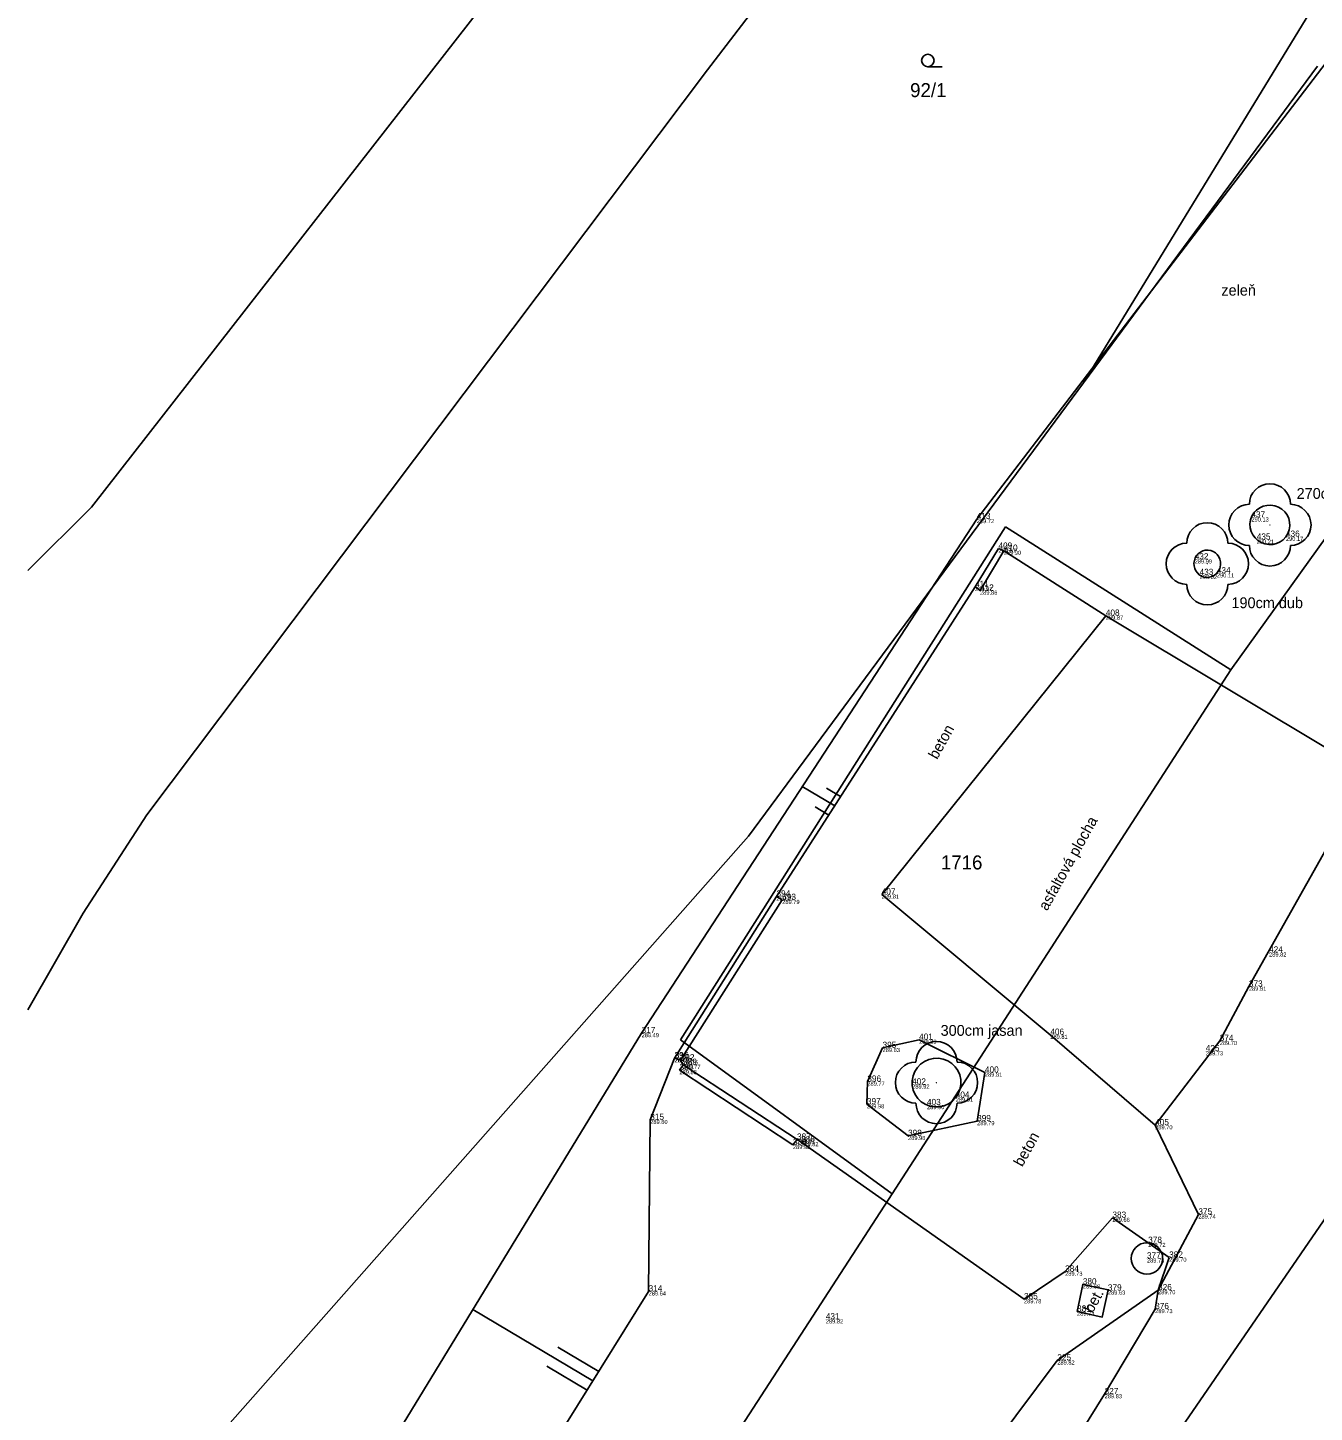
# Model space of a CAD drawing. Extents: x -805057 to -804930, y -994399 to -994240.
# Drawn here: x -805055.46 to -805024.17, y -994307.89 to -994274.22 of the extents above; entities that cross this region are included whole.
import ezdxf

# ---------------------------------------------------------------- set-up
doc = ezdxf.new("R2010")
doc.units = 0
for name, color, linetype in [('bod cislo', 7, 'Continuous'), ('bod pozice', 7, 'Continuous'), ('bod výška', 7, 'Continuous'), ('kanalizace', 7, 'Continuous'), ('Katastralni mapa', 7, 'Continuous'), ('komunikace', 7, 'Continuous'), ('plot', 7, 'Continuous'), ('popis', 7, 'Continuous'), ('strom', 7, 'Continuous'), ('svah', 7, 'Continuous'), ('šrafy', 7, 'Continuous')]:
    doc.layers.add(name, color=color, linetype=linetype)

msp = doc.modelspace()

# ---------------------------------------------------------------- linework, layer by layer
at = {"layer": 'bod pozice'}
for p, q in [((-805032.38, -994286.17), (-805032.38, -994286.17)), ((-805025.7, -994286.13), (-805025.7, -994286.13)), ((-805025.57, -994286.67), (-805025.57, -994286.67)), ((-805024.86, -994286.6), (-805024.86, -994286.6)), ((-805031.85, -994286.89), (-805031.85, -994286.89)), ((-805031.72, -994286.94), (-805031.72, -994286.94)), ((-805027.08, -994287.15), (-805027.08, -994287.15)), ((-805026.96, -994287.53), (-805026.96, -994287.53)), ((-805026.54, -994287.49), (-805026.54, -994287.49)), ((-805032.42, -994287.82), (-805032.42, -994287.82)), ((-805032.3, -994287.91), (-805032.3, -994287.91)), ((-805029.24, -994288.52), (-805029.24, -994288.52)), ((-805037.25, -994295.35), (-805037.25, -994295.35)), ((-805037.11, -994295.43), (-805037.11, -994295.43)), ((-805034.69, -994295.3), (-805034.69, -994295.3)), ((-805025.27, -994296.71), (-805025.27, -994296.71)), ((-805025.76, -994297.54), (-805025.76, -994297.54)), ((-805040.53, -994298.67), (-805040.53, -994298.67)), ((-805030.59, -994298.71), (-805030.59, -994298.71)), ((-805034.67, -994299.03), (-805034.67, -994299.03)), ((-805033.78, -994298.83), (-805033.78, -994298.83)), ((-805026.81, -994299.11), (-805026.81, -994299.11)), ((-805026.47, -994298.86), (-805026.47, -994298.86)), ((-805039.73, -994299.28), (-805039.73, -994299.28)), ((-805039.72, -994299.28), (-805039.72, -994299.28)), ((-805039.58, -994299.33), (-805039.58, -994299.33)), ((-805039.52, -994299.44), (-805039.52, -994299.44)), ((-805039.61, -994299.57), (-805039.61, -994299.57)), ((-805032.18, -994299.63), (-805032.18, -994299.63)), ((-805035.04, -994299.85), (-805035.04, -994299.85)), ((-805033.95, -994299.92), (-805033.95, -994299.92)), ((-805035.05, -994300.4), (-805035.05, -994300.4)), ((-805033.59, -994300.42), (-805033.59, -994300.42)), ((-805032.89, -994300.24), (-805032.89, -994300.24)), ((-805040.32, -994300.78), (-805040.32, -994300.78)), ((-805032.37, -994300.81), (-805032.37, -994300.81)), ((-805034.05, -994301.17), (-805034.05, -994301.17)), ((-805028.04, -994300.91), (-805028.04, -994300.91)), ((-805036.85, -994301.39), (-805036.85, -994301.39)), ((-805036.75, -994301.26), (-805036.75, -994301.26)), ((-805036.65, -994301.32), (-805036.65, -994301.32)), ((-805029.08, -994303.16), (-805029.08, -994303.16)), ((-805026.99, -994303.08), (-805026.99, -994303.08)), ((-805028.21, -994303.77), (-805028.21, -994303.77)), ((-805028.24, -994304.15), (-805028.24, -994304.15)), ((-805027.7, -994304.13), (-805027.7, -994304.13)), ((-805030.23, -994304.47), (-805030.23, -994304.47)), ((-805029.8, -994304.78), (-805029.8, -994304.78)), ((-805040.36, -994304.95), (-805040.36, -994304.95)), ((-805031.23, -994305.14), (-805031.23, -994305.14)), ((-805029.19, -994304.93), (-805029.19, -994304.93)), ((-805027.97, -994304.92), (-805027.97, -994304.92)), ((-805029.94, -994305.44), (-805029.94, -994305.44)), ((-805028.04, -994305.38), (-805028.04, -994305.38)), ((-805036.05, -994305.63), (-805036.05, -994305.63)), ((-805030.42, -994306.63), (-805030.42, -994306.63)), ((-805029.27, -994307.45), (-805029.27, -994307.45))]:
    msp.add_line(p, q, dxfattribs=at)
at = {"layer": 'kanalizace'}
msp.add_circle((-805028.24, -994304.15), 0.382, dxfattribs=at)
at = {"layer": 'Katastralni mapa'}
for points in [[(-805018.71, -994264.73), (-805029.78, -994282.86)], [(-805031.83, -994265.99), (-805038.93, -994275.25)], [(-805043.31, -994272.29), (-805053.91, -994285.88)], [(-805033.57, -994275.17), (-805033.219, -994275.17)], [(-805024.09, -994275.16), (-805029.78, -994282.86)], [(-805038.93, -994275.25), (-805052.56, -994293.36)], [(-805029.78, -994282.86), (-805037.93, -994293.88)], [(-805055.46, -994287.421), (-805053.91, -994285.88)], [(-805023.45, -994286.01), (-805026.2, -994289.84)], [(-805031.68, -994286.36), (-805039.58, -994298.83)], [(-805026.2, -994289.84), (-805031.68, -994286.36)], [(-805034.44, -994302.58), (-805026.2, -994289.84)], [(-805052.56, -994293.36), (-805054.11, -994295.75)], [(-805037.93, -994293.88), (-805055.46, -994313.714)], [(-805054.11, -994295.75), (-805055.46, -994298.108)], [(-805039.58, -994298.83), (-805034.44, -994302.58)], [(-805046.31, -994320.89), (-805034.44, -994302.58)]]:
    msp.add_lwpolyline(points, dxfattribs=at)
msp.add_circle((-805033.569, -994275.02), 0.151, dxfattribs=at)
at = {"layer": 'komunikace'}
for p, q in [((-805032.42, -994287.82), (-805031.85, -994286.89)), ((-805031.72, -994286.94), (-805032.3, -994287.91)), ((-805031.85, -994286.89), (-805031.72, -994286.94)), ((-805031.72, -994286.94), (-805029.24, -994288.52)), ((-805037.25, -994295.35), (-805032.42, -994287.82)), ((-805032.3, -994287.91), (-805032.42, -994287.82)), ((-805034.69, -994295.3), (-805029.24, -994288.52)), ((-805029.24, -994288.52), (-805022.85, -994292.36)), ((-805025.76, -994297.54), (-805022.85, -994292.36)), ((-805039.73, -994299.28), (-805037.25, -994295.35)), ((-805037.11, -994295.43), (-805039.58, -994299.33)), ((-805037.25, -994295.35), (-805037.11, -994295.43)), ((-805034.69, -994295.3), (-805030.59, -994298.71)), ((-805026.47, -994298.86), (-805025.76, -994297.54)), ((-805030.59, -994298.71), (-805028.04, -994300.91)), ((-805034.67, -994299.03), (-805035.04, -994299.85)), ((-805033.78, -994298.83), (-805034.67, -994299.03)), ((-805032.18, -994299.63), (-805033.78, -994298.83)), ((-805026.47, -994298.86), (-805028.04, -994300.91)), ((-805039.58, -994299.33), (-805039.73, -994299.28)), ((-805039.61, -994299.57), (-805039.52, -994299.44)), ((-805039.52, -994299.44), (-805039.58, -994299.33)), ((-805039.52, -994299.44), (-805036.75, -994301.26)), ((-805036.85, -994301.39), (-805039.61, -994299.57)), ((-805032.18, -994299.63), (-805032.37, -994300.81)), ((-805035.04, -994299.85), (-805035.05, -994300.4)), ((-805035.05, -994300.4), (-805034.05, -994301.17)), ((-805028.28, -994309.54), (-805022, -994300.4)), ((-805034.05, -994301.17), (-805032.37, -994300.81)), ((-805026.99, -994303.08), (-805028.04, -994300.91)), ((-805036.75, -994301.26), (-805036.85, -994301.39)), ((-805036.65, -994301.32), (-805036.75, -994301.26)), ((-805031.23, -994305.14), (-805036.65, -994301.32)), ((-805030.23, -994304.47), (-805029.08, -994303.16)), ((-805029.08, -994303.16), (-805027.7, -994304.13)), ((-805027.97, -994304.92), (-805026.99, -994303.08)), ((-805027.7, -994304.13), (-805027.97, -994304.92)), ((-805031.23, -994305.14), (-805030.23, -994304.47)), ((-805028.04, -994305.38), (-805027.97, -994304.92)), ((-805029.27, -994307.45), (-805028.04, -994305.38)), ((-805033.55, -994314.32), (-805029.27, -994307.45))]:
    msp.add_line(p, q, dxfattribs=at)
msp.add_lwpolyline([(-805029.94, -994305.44), (-805029.8, -994304.78), (-805029.187, -994304.914), (-805029.327, -994305.574)], close=True, dxfattribs=at)
at = {"layer": 'plot'}
for p, q in [((-805040.53, -994298.67), (-805032.38, -994286.17)), ((-805047.18, -994309.56), (-805040.53, -994298.67))]:
    msp.add_line(p, q, dxfattribs=at)
msp.add_lwpolyline([(-805032.38, -994286.17), (-805016.94, -994265.99), (-805019.51, -994262.99)], dxfattribs=at)
at = {"layer": 'strom'}
for centre in [(-805025.25, -994286.312), (-805026.772, -994287.258), (-805033.358, -994299.874)]:
    msp.add_circle(centre, 0.0005, dxfattribs=at)
for centre, start, end in [((-805025.25, -994285.812), 0, 180), ((-805025.75, -994286.312), 90, 270), ((-805024.75, -994286.312), 270, 90), ((-805026.772, -994286.758), 0, 180), ((-805027.272, -994287.258), 90, 270), ((-805026.272, -994287.258), 270, 90), ((-805025.25, -994286.812), 180, 360), ((-805026.772, -994287.758), 180, 360), ((-805033.358, -994299.374), 0, 180), ((-805033.858, -994299.874), 90, 270), ((-805032.858, -994299.874), 270, 90), ((-805033.358, -994300.374), 180, 360)]:
    msp.add_arc(centre, 0.5, start, end, dxfattribs=at)
for centre, major_axis, ratio in [((-805025.25, -994286.312), (0.47, -0.121), 0.986953), ((-805026.772, -994287.258), (-0.017, -0.332), 0.977537), ((-805033.358, -994299.874), (0.592, -0.047), 0.999095)]:
    msp.add_ellipse(centre, major_axis=major_axis, ratio=ratio, dxfattribs=at)
at = {"layer": 'svah'}
for p, q in [((-805040.32, -994300.78), (-805039.73, -994299.28)), ((-805040.36, -994304.95), (-805040.32, -994300.78)), ((-805043.07, -994309.3), (-805040.36, -994304.95)), ((-805030.42, -994306.63), (-805027.97, -994304.92)), ((-805032.96, -994310.02), (-805030.42, -994306.63))]:
    msp.add_line(p, q, dxfattribs=at)
at = {"layer": 'šrafy'}
for p, q in [((-805035.834, -994293.142), (-805036.621, -994292.675)), ((-805035.693, -994292.916), (-805036.035, -994292.713)), ((-805035.975, -994293.37), (-805036.308, -994293.172)), ((-805041.715, -994307.125), (-805044.634, -994305.391)), ((-805041.574, -994306.899), (-805042.565, -994306.31)), ((-805041.857, -994307.352), (-805042.838, -994306.769))]:
    msp.add_line(p, q, dxfattribs=at)

# ---------------------------------------------------------------- texts
at = {"layer": 'bod cislo'}
for s, p in [('413    ', (-805032.38, -994286.17)), ('437    ', (-805025.7, -994286.13)), ('435    ', (-805025.57, -994286.67)), ('436    ', (-805024.86, -994286.6)), ('409    ', (-805031.85, -994286.89)), ('410    ', (-805031.72, -994286.94)), ('432    ', (-805027.08, -994287.15)), ('434    ', (-805026.54, -994287.49)), ('411    ', (-805032.42, -994287.82)), ('433    ', (-805026.96, -994287.53)), ('412    ', (-805032.3, -994287.91)), ('408    ', (-805029.24, -994288.52)), ('394    ', (-805037.25, -994295.35)), ('393    ', (-805037.11, -994295.43)), ('407    ', (-805034.69, -994295.3)), ('424    ', (-805025.27, -994296.71)), ('424    ', (-805025.27, -994296.71)), ('373    ', (-805025.76, -994297.54)), ('317    ', (-805040.53, -994298.67)), ('401    ', (-805033.78, -994298.83)), ('406    ', (-805030.59, -994298.71)), ('374    ', (-805026.47, -994298.86)), ('391    ', (-805039.73, -994299.28)), ('316    ', (-805039.72, -994299.28)), ('395    ', (-805034.67, -994299.03)), ('425    ', (-805026.81, -994299.11)), ('390    ', (-805039.61, -994299.57)), ('392    ', (-805039.58, -994299.33)), ('389    ', (-805039.52, -994299.44)), ('400    ', (-805032.18, -994299.63)), ('396    ', (-805035.04, -994299.85)), ('402    ', (-805033.95, -994299.92)), ('404    ', (-805032.89, -994300.24)), ('397    ', (-805035.05, -994300.4)), ('403    ', (-805033.59, -994300.42)), ('315    ', (-805040.32, -994300.78)), ('399    ', (-805032.37, -994300.81)), ('405    ', (-805028.04, -994300.91)), ('387    ', (-805036.75, -994301.26)), ('386    ', (-805036.65, -994301.32)), ('398    ', (-805034.05, -994301.17)), ('388    ', (-805036.85, -994301.39)), ('383    ', (-805029.08, -994303.16)), ('375    ', (-805026.99, -994303.08)), ('378    ', (-805028.21, -994303.77)), ('377    ', (-805028.24, -994304.15)), ('382    ', (-805027.7, -994304.13)), ('384    ', (-805030.23, -994304.47)), ('314    ', (-805040.36, -994304.95)), ('380    ', (-805029.8, -994304.78)), ('379    ', (-805029.19, -994304.93)), ('326    ', (-805027.97, -994304.92)), ('385    ', (-805031.23, -994305.14)), ('431    ', (-805036.05, -994305.63)), ('381    ', (-805029.94, -994305.44)), ('376    ', (-805028.04, -994305.38)), ('325    ', (-805030.42, -994306.63)), ('327    ', (-805029.27, -994307.45))]:
    msp.add_text(s, height=0.15, dxfattribs=at).set_placement(p)
at = {"layer": 'bod výška'}
for s, p in [('289.72  ', (-805032.38, -994286.27)), ('290.13  ', (-805025.7, -994286.23)), ('290.21  ', (-805025.57, -994286.77)), ('290.17  ', (-805024.86, -994286.7)), ('289.97  ', (-805031.85, -994286.99)), ('289.90  ', (-805031.72, -994287.04)), ('289.99  ', (-805027.08, -994287.25)), ('290.02  ', (-805026.96, -994287.63)), ('290.11  ', (-805026.54, -994287.59)), ('289.97  ', (-805032.42, -994287.92)), ('289.86  ', (-805032.3, -994288.01)), ('289.87  ', (-805029.24, -994288.62)), ('289.87  ', (-805037.25, -994295.45)), ('289.79  ', (-805037.11, -994295.53)), ('289.81  ', (-805034.69, -994295.4)), ('289.82  ', (-805025.27, -994296.81)), ('289.81  ', (-805025.76, -994297.64)), ('289.49  ', (-805040.53, -994298.77)), ('289.81  ', (-805030.59, -994298.81)), ('289.83  ', (-805034.67, -994299.13)), ('289.89  ', (-805033.78, -994298.93)), ('289.73  ', (-805026.81, -994299.21)), ('289.70  ', (-805026.47, -994298.96)), ('289.83  ', (-805039.73, -994299.38)), ('289.72  ', (-805039.72, -994299.38)), ('289.76  ', (-805039.58, -994299.43)), ('289.77  ', (-805039.52, -994299.54)), ('289.83  ', (-805039.61, -994299.67)), ('289.81  ', (-805032.18, -994299.73)), ('289.77  ', (-805035.04, -994299.95)), ('289.92  ', (-805033.95, -994300.02)), ('289.98  ', (-805035.05, -994300.5)), ('289.90  ', (-805033.59, -994300.52)), ('289.91  ', (-805032.89, -994300.34)), ('289.80  ', (-805040.32, -994300.88)), ('289.79  ', (-805032.37, -994300.91)), ('289.98  ', (-805034.05, -994301.27)), ('289.70  ', (-805028.04, -994301.01)), ('289.92  ', (-805036.85, -994301.49)), ('289.83  ', (-805036.75, -994301.36)), ('289.82  ', (-805036.65, -994301.42)), ('289.66  ', (-805029.08, -994303.26)), ('289.74  ', (-805026.99, -994303.18)), ('289.72  ', (-805028.21, -994303.87)), ('289.74  ', (-805028.24, -994304.25)), ('289.70  ', (-805027.7, -994304.23)), ('289.73  ', (-805030.23, -994304.57)), ('289.68  ', (-805029.8, -994304.88)), ('289.64  ', (-805040.36, -994305.05)), ('289.78  ', (-805031.23, -994305.24)), ('289.63  ', (-805029.19, -994305.03)), ('289.70  ', (-805027.97, -994305.02)), ('289.73  ', (-805029.94, -994305.54)), ('289.73  ', (-805028.04, -994305.48)), ('289.82  ', (-805036.05, -994305.73)), ('289.82  ', (-805030.42, -994306.73)), ('289.83  ', (-805029.27, -994307.55))]:
    msp.add_text(s, height=0.1, dxfattribs=at).set_placement(p)
at = {"layer": 'Katastralni mapa'}
for s, p in [('92/1', (-805034, -994275.91)), ('1716', (-805033.253, -994294.69))]:
    msp.add_text(s, height=0.34, dxfattribs=at).set_placement(p)
at = {"layer": 'popis'}
for s, height, p in [('zeleň', 0.2629, (-805026.431, -994280.736)), ('270cm lípa', 0.2629, (-805024.6, -994285.679)), ('190cm dub', 0.2629, (-805026.185, -994288.337)), ('300cm jasan', 0.26289, (-805033.258, -994298.736))]:
    msp.add_text(s, height=height, dxfattribs=at).set_placement(p)
for s, height, p in [('beton', 0.2629, (-805033.344, -994292.031)), ('asfaltová plocha', 0.26289, (-805030.667, -994295.714)), ('beton', 0.2629, (-805031.272, -994301.938)), ('bet.', 0.2629, (-805029.565, -994305.495))]:
    msp.add_text(s, height=height, rotation=60.8904, dxfattribs=at).set_placement(p)

doc.saveas('drawing.dxf')
